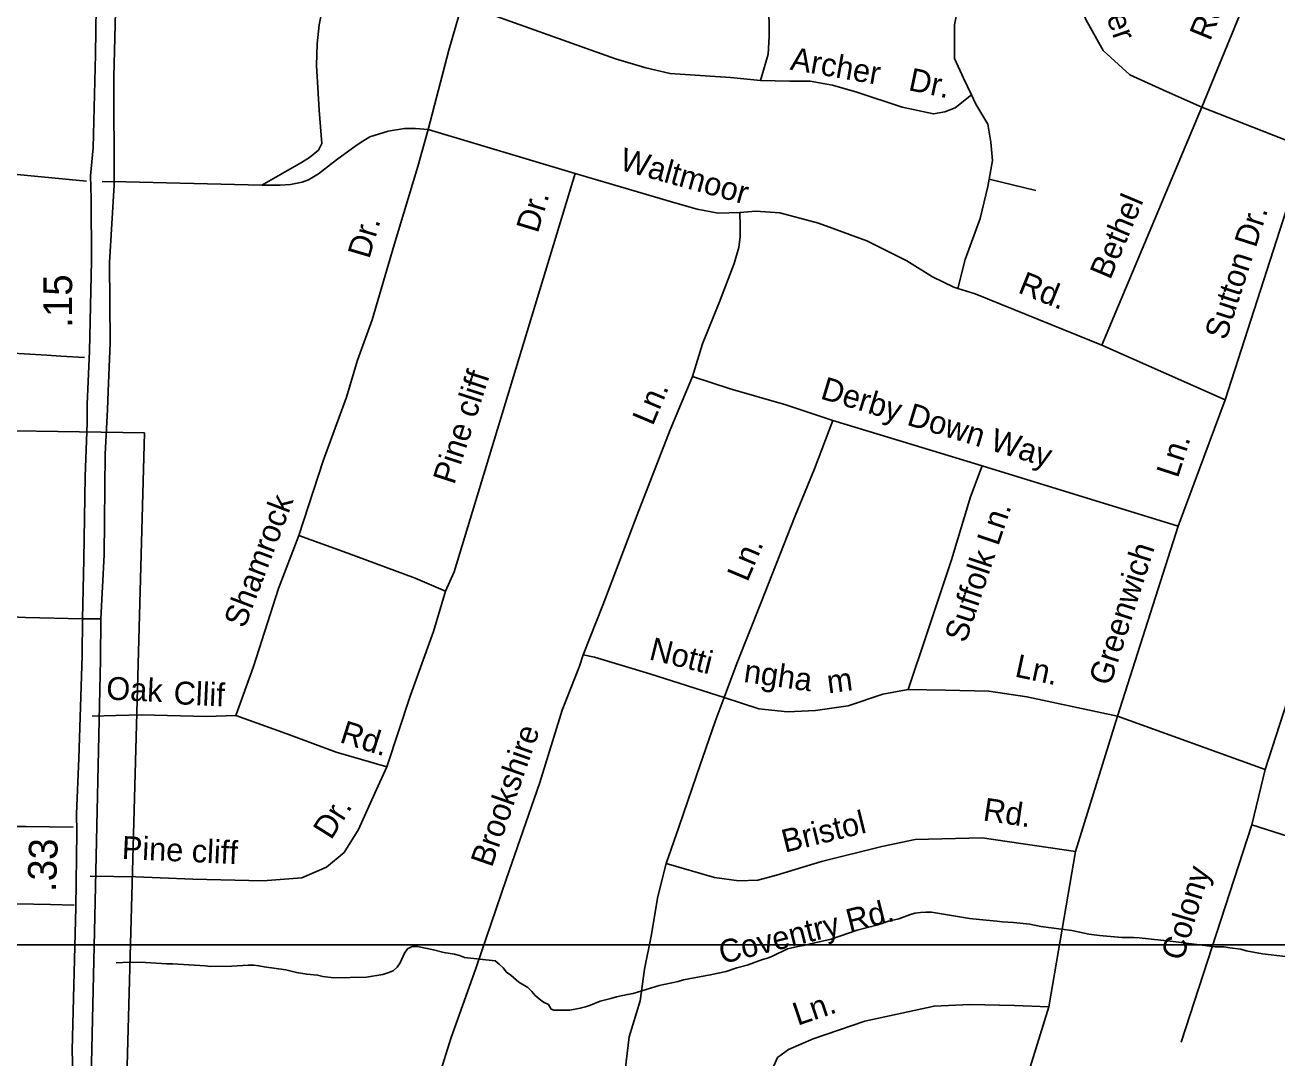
# Model space of a CAD drawing. Extents: x 1945482 to 2853149, y 66427 to 1015778.
# Drawn here: x 2335176 to 2338758, y 154277 to 157233 of the extents above; entities that cross this region are included whole.
import ezdxf

# ---------------------------------------------------------------- set-up
doc = ezdxf.new("R2010")
doc.units = 0
for name, color, linetype in [('Old_Level_10', 7, 'Continuous'), ('Old_Level_17', 7, 'Continuous'), ('Old_Level_29', 7, 'Continuous'), ('Old_Level_32', 7, 'Continuous'), ('Old_Level_35', 7, 'Continuous'), ('Old_Level_48', 7, 'Continuous'), ('Old_Level_49', 7, 'Continuous'), ('Old_Level_59', 7, 'Continuous'), ('Old_Level_63', 7, 'Continuous')]:
    doc.layers.add(name, color=color, linetype=linetype)

msp = doc.modelspace()

# ---------------------------------------------------------------- linework, layer by layer
at = {"layer": 'Old_Level_29'}
for points in [[(2335381.6, 157421.3), (2335377.6, 157148.3), (2335370.7, 156880.9), (2335363, 156800.8), (2335365.2, 156736.3), (2335366.3, 156557.7), (2335360.9, 156300), (2335353.8, 156147.8), (2335353.8, 156094.3), (2335347.9, 155940.6), (2335344.1, 155703.4), (2335340.8, 155534.1)], [(2335393.4, 155533.8), (2335402.8, 155716.4), (2335405.8, 156004.4), (2335411.8, 156132.6), (2335414.3, 156184.4), (2335420.1, 156323.2), (2335417.9, 156553.4), (2335430.8, 156775), (2335430.5, 157084.3), (2335438.7, 157420.3)], [(2335340.8, 155534.1), (2335339.2, 155428.3), (2335330.1, 155134.4), (2335323.4, 154975.9), (2335323.9, 154923.7), (2335321, 154707.7), (2335310.7, 154299.7), (2335312.9, 154231.4), (2335306.8, 154006.8), (2335303.5, 153814.6)], [(2335355.1, 153789.8), (2335366.5, 154261.2), (2335375.6, 154682), (2335391.9, 155416.1), (2335393.4, 155533.8)]]:
    msp.add_lwpolyline(points, dxfattribs=at)
at = {"layer": 'Old_Level_32'}
for points in [[(2335340.8, 155534.1), (2335177.3, 155537.5), (2334739.3, 155558.1), (2334130.3, 155561.6), (2333990.2, 155561.6)], [(2335393.4, 155533.8), (2335340.8, 155534.1)]]:
    msp.add_lwpolyline(points, dxfattribs=at)
at = {"layer": 'Old_Level_35'}
for p, q in [((2338542.8, 156997.6), (2338680.8, 157334.2)), ((2338256.4, 156317.1), (2338542.8, 156997.6)), ((2338542.8, 156997.6), (2338841.2, 156880.5)), ((2336329.3, 156933.8), (2336749.7, 156808.4)), ((2338609.7, 156160.6), (2338841.2, 156880.5)), ((2337934.5, 156791.6), (2338068, 156759.3)), ((2338256.4, 156317.1), (2338609.7, 156160.6)), ((2335346.3, 156281), (2335278.5, 156285.5)), ((2338475.6, 155798.6), (2338609.7, 156160.6)), ((2337914.1, 155971.9), (2338475.6, 155798.6)), ((2338301.3, 155255.3), (2338475.6, 155798.6)), ((2338181.6, 154867.7), (2338301.3, 155255.3)), ((2335245.7, 154938.7), (2335313.4, 154938)), ((2338105.3, 154423.1), (2338181.6, 154867.7)), ((2335316.3, 154714.3), (2335248.6, 154715.9))]:
    msp.add_line(p, q, dxfattribs=at)
for points in [[(2335853.4, 156774.9), (2335967, 156839.4), (2335990.4, 156854.1), (2336015.5, 156875.1), (2336024.9, 156893.6), (2336017.2, 156989.4), (2336010.2, 157117.2), (2336011.7, 157179.2), (2336017.4, 157233.3), (2336044.4, 157364.7), (2336090.4, 157510.6), (2336165.2, 157695.3), (2336268.4, 157923.6), (2336387.3, 158154.4), (2336460.7, 158265.3), (2336598.3, 158428.9), (2336737.4, 158616.6)], [(2329074.5, 157614.2), (2329735.5, 156994.4), (2329904, 156887), (2330064.9, 156787.4), (2330306.6, 156694.5), (2332978.6, 156610), (2333405, 156611), (2333711.5, 156626.4), (2334109.8, 156703), (2334497.5, 156778.2), (2334742.6, 156808.8), (2335033.7, 156816.5), (2335352.2, 156786.3)], [(2337883.5, 157032.6), (2337861.1, 157080.3), (2337835, 157137), (2337835, 157193.7), (2337835, 157232.9), (2337843.7, 157276.5), (2337869.8, 157346.3), (2337900.3, 157433.5), (2337952.6, 157525.1), (2338004.9, 157577.4), (2338083.7, 157611.9)], [(2338083.7, 157611.9), (2338179.7, 157337.5), (2338211.3, 157249), (2338260.9, 157159.9), (2338337.1, 157090.1), (2338441.7, 157042.2), (2338542.8, 156997.6)], [(2336426.3, 157292), (2336388.3, 157161.3), (2336329.3, 156933.8)], [(2336426.3, 157292), (2336865.5, 157135.7)], [(2337280.4, 157074.5), (2337302.6, 157149.7), (2337305.4, 157199.8), (2337305.4, 157244.4), (2337297.1, 157301.5)], [(2336865.5, 157135.7), (2336951.8, 157110.7), (2337021.4, 157094), (2337107.7, 157088.4), (2337194.1, 157082.8), (2337280.4, 157074.5)], [(2337883.5, 157032.6), (2337837.1, 156995.8), (2337807.6, 156984.6), (2337775.5, 156978.6), (2337685.1, 156997.5), (2337556, 157041), (2337486.4, 157060.5), (2337422.4, 157071.7), (2337363.9, 157071.7), (2337280.4, 157074.5)], [(2337934.5, 156791.6), (2337943.9, 156844.8), (2337939.5, 156897.2), (2337930.8, 156949.5), (2337896, 157006.2), (2337883.5, 157032.6)], [(2335397.2, 156785.3), (2335464.8, 156783.7), (2335853.4, 156774.9), (2335905.6, 156775), (2335935.4, 156776.1), (2335969.2, 156783.4), (2335987, 156790), (2336016.2, 156807.2), (2336066.8, 156847.3), (2336123.3, 156887.6), (2336142.2, 156900), (2336162.3, 156913.1), (2336215.5, 156929), (2336261.9, 156936.9), (2336293.5, 156936.9), (2336329.3, 156933.8)], [(2336329.3, 156933.8), (2336299.8, 156828.4), (2336232.1, 156604.2), (2336168.9, 156389.2), (2336127.6, 156273.4), (2336095.6, 156168.1), (2336028.7, 155985.3), (2335959.3, 155772.5)], [(2336379.5, 155613.2), (2336403.6, 155668.3), (2336749.7, 156808.4)], [(2336749.7, 156808.4), (2337041.9, 156721.8), (2337098.7, 156706), (2337159.2, 156694.3), (2337220.8, 156696.7)], [(2337845.3, 156479.3), (2337865.5, 156561.4), (2337909, 156679.1), (2337930.8, 156770.7), (2337934.5, 156791.6)], [(2337220.8, 156696.7), (2337266.9, 156700.5), (2337335.1, 156695.3), (2337446.5, 156665.6), (2337584.4, 156615.2), (2337698.9, 156557.7), (2337772.6, 156512.4), (2337833.8, 156483), (2337845.3, 156479.3)], [(2337085.8, 156227.3), (2337113.9, 156320.3), (2337163.3, 156440.4), (2337205.3, 156550.8), (2337217.9, 156596.2), (2337222.5, 156627.5), (2337222.5, 156657.3), (2337220.8, 156696.7)], [(2337845.3, 156479.3), (2337894.7, 156463.4), (2338256.4, 156317.1)], [(2335278.5, 156285.5), (2335238.5, 156288.1), (2335076, 156297.8), (2334928.2, 156291.9), (2334830.3, 156288), (2334764.7, 156277.6), (2334729.8, 156256.2), (2334698.9, 156222.8), (2334678.6, 156181.9), (2334664.6, 156077.3), (2334666.4, 156017.7)], [(2336773, 155430.5), (2336829.4, 155572.9), (2336927.2, 155830.8), (2337021.6, 156074.7), (2337085.8, 156227.3)], [(2337085.8, 156227.3), (2337193.2, 156191.5), (2337352.9, 156145.9), (2337486.9, 156101)], [(2339240, 156172.5), (2339110.7, 156089.1), (2339067.1, 156034.5), (2339001.8, 155887.3), (2338838.3, 155456.6), (2338723.9, 155102.1), (2338685.7, 154944), (2338484.1, 154322.4)], [(2337176, 155308.6), (2337212.1, 155405.8), (2337281.4, 155578.9), (2337379.5, 155828.6), (2337434.3, 155963.1), (2337486.9, 156101)], [(2337486.9, 156101), (2337622.4, 156060.4), (2337914.1, 155971.9)], [(2337703.1, 155331.4), (2337756.8, 155493.7), (2337826.6, 155702.2), (2337881.5, 155882.6), (2337914.1, 155971.9)], [(2335959.3, 155772.5), (2335901.3, 155620.2), (2335830.1, 155397.5), (2335779.5, 155257.3)], [(2335959.3, 155772.5), (2336097.2, 155722.1), (2336292.1, 155649.7), (2336379.5, 155613.2)], [(2336211.3, 155110.3), (2336279.4, 155315.1), (2336344.4, 155497.6), (2336379.5, 155613.2)], [(2336351.5, 154195.5), (2336394.3, 154333.1), (2336466.4, 154536.1), (2336552.3, 154787.7), (2336649.3, 155065.6), (2336713.3, 155272.2), (2336762.2, 155398.2), (2336773, 155430.5)], [(2336773, 155430.5), (2336805.4, 155423.9), (2336963.2, 155376), (2337176, 155308.6)], [(2337010.6, 154833.7), (2337046.6, 154937.2), (2337096.8, 155085.2), (2337150.8, 155239.6), (2337176, 155308.6)], [(2337176, 155308.6), (2337275.4, 155276.4), (2337357.7, 155267.9), (2337437.7, 155271), (2337531, 155284.6), (2337629.8, 155318.3), (2337703.1, 155331.4)], [(2337703.1, 155331.4), (2337809.5, 155329.7), (2337933.4, 155326.4), (2338042.3, 155310.7), (2338301.3, 155255.3)], [(2335368, 155254.8), (2335435.7, 155256.7), (2335509.3, 155258.7), (2335695.6, 155254), (2335779.5, 155257.3)], [(2335779.5, 155257.3), (2335925.6, 155205), (2336065.9, 155152.4), (2336211.3, 155110.3)], [(2338301.3, 155255.3), (2338723.9, 155102.1)], [(2335362.6, 154797.5), (2335429.9, 154796.5), (2335493.5, 154795.7), (2335655.9, 154788.3), (2335856.3, 154784.1), (2335967.9, 154792.4), (2336038.9, 154823.5), (2336089.1, 154865.5), (2336130.4, 154931.1), (2336176.6, 155035), (2336211.3, 155110.3)], [(2338685.7, 154944), (2339045.3, 154829.5), (2339410.4, 154720.4), (2339587.6, 154667.7)], [(2335248.6, 154715.9), (2335152.6, 154718.2), (2334998.6, 154720.3), (2334930.3, 154721.5), (2334911.9, 154730.7), (2334910.6, 154762.8), (2334916.8, 154913), (2334918.1, 154929.1), (2334928.1, 154933.5), (2334981.7, 154939.5), (2335178, 154939.4), (2335245.7, 154938.7)], [(2337010.6, 154833.7), (2337148.4, 154793.2), (2337218.7, 154784.2), (2337272.8, 154786.3), (2337326, 154800.2), (2337454.8, 154839.4), (2337627, 154882), (2337722.4, 154901.9), (2337914.2, 154907.5), (2338181.6, 154867.7)], [(2336881.9, 154146.6), (2336904.2, 154337.5), (2336936.2, 154440.8), (2336948.7, 154531.3), (2336967, 154625.9), (2336986.5, 154738.9), (2337010.6, 154833.7)], [(2337296.8, 154020.9), (2337306.6, 154179.1), (2337314.2, 154245.7), (2337328.6, 154278.1), (2337359.9, 154301.4), (2337430.5, 154332.1), (2337578.9, 154382.2), (2337777, 154425.8), (2337878.9, 154429.9), (2338007, 154427.1), (2338105.3, 154423.1)], [(2338018, 154049.4), (2338033.9, 154154.1), (2338052.1, 154250.6), (2338105.3, 154423.1)]]:
    msp.add_lwpolyline(points, dxfattribs=at)
at = {"layer": 'Old_Level_48'}
for points in [[(2335517.6, 156066.1), (2334898, 156075.8)], [(2339957.8, 153962.6), (2338392.3, 154026.4), (2338264.7, 153918.4), (2338225.5, 153756.4), (2338245.7, 153020.7), (2338302.5, 152756.7), (2338029.2, 152666.4), (2336836.7, 153157.4), (2336493.1, 153250.7), (2335452.8, 153697.5), (2335517.6, 156066.1)]]:
    msp.add_lwpolyline(points, dxfattribs=at)
at = {"layer": 'Old_Level_49'}
for points in [[(2335517.6, 156066.1), (2334898, 156075.8)], [(2339957.8, 153962.6), (2338392.3, 154026.4), (2338264.7, 153918.4), (2338225.5, 153756.4), (2338245.7, 153020.7), (2338302.5, 152756.7), (2338029.2, 152666.4), (2336836.7, 153157.4), (2336493.1, 153250.7), (2335452.8, 153697.5), (2335517.6, 156066.1)]]:
    msp.add_lwpolyline(points, dxfattribs=at)
at = {"layer": 'Old_Level_59'}
for points in [[(2338782.2, 154567.9), (2338716.5, 154574.8), (2338669.5, 154583.6), (2338654.5, 154588.6), (2338623, 154592.1), (2338606.7, 154595.1), (2338581, 154595.3), (2338461.2, 154610.8), (2338363.5, 154621.1), (2338347, 154622.1), (2338314.7, 154622.2), (2338281.5, 154624.3), (2338250.2, 154627.6), (2338219.2, 154631.6), (2338170.5, 154641.5), (2338082.7, 154652.9), (2338051.2, 154659.9), (2338003.7, 154664.9), (2337971.7, 154666.5), (2337956.7, 154668.7), (2337925.5, 154671.2), (2337878, 154676.3), (2337769.2, 154693.9), (2337753.2, 154694.2), (2337738.2, 154693.5), (2337721.7, 154691.4), (2337706.5, 154686.6), (2337676.5, 154675), (2337646, 154668.4), (2337616.2, 154658.2), (2337556.5, 154642.5), (2337482, 154617.2), (2337435.7, 154606.8), (2337403.7, 154598.7), (2337387.5, 154596.1), (2337357.7, 154589.1), (2337314.5, 154568.5), (2337300.5, 154563), (2337286, 154558.8), (2337242.5, 154542.6), (2337212.2, 154535.5), (2337182.2, 154525), (2337136.5, 154514.8), (2337059.7, 154500.6), (2337044.7, 154495.9), (2336990, 154484.6), (2336915.7, 154461.2), (2336900.2, 154459.2), (2336868, 154452.5), (2336852.5, 154447.3), (2336822, 154439.9), (2336793.5, 154428.2), (2336779.2, 154423.3), (2336764.5, 154419.4), (2336734.5, 154414.1), (2336689.2, 154413.7), (2336681.7, 154417.1), (2336673.7, 154430.1)], [(2336673.7, 154430.1), (2336659.5, 154436.7), (2336647.2, 154445.9), (2336635.7, 154456.1), (2336626.2, 154467.8), (2336615, 154478.7), (2336589.2, 154494.4), (2336565.7, 154513.9), (2336553.5, 154522.6), (2336543.7, 154534.7), (2336533, 154545.3), (2336521.2, 154555.2), (2336433.7, 154564.3), (2336419, 154570.5), (2336404.5, 154574), (2336374.5, 154579.3), (2336344.5, 154586.9), (2336299.2, 154596.4), (2336283.7, 154595.8), (2336270.7, 154589.3), (2336261.7, 154577), (2336249.5, 154549.4), (2336240.7, 154536.8), (2336229, 154526.3), (2336214.5, 154520.3), (2336199.7, 154516.4), (2336153, 154508.5), (2336059.5, 154506.5), (2336028.2, 154510.3), (2336012.7, 154513.9), (2335982.2, 154516.7), (2335952.5, 154521.9), (2335922.7, 154529.3), (2335860.7, 154538), (2335845.5, 154541), (2335830.5, 154542.5), (2335814.5, 154542.7), (2335768.2, 154539.8), (2335706.7, 154538.7), (2335691.5, 154540.5), (2335644.5, 154544), (2335598, 154546.3), (2335582, 154546.2), (2335520.5, 154550.2), (2335474.2, 154551.1), (2335437, 154549.4)]]:
    msp.add_lwpolyline(points, dxfattribs=at)
at = {"layer": 'Old_Level_63'}
msp.add_lwpolyline([(2346064.1, 148689.8), (2332656.4, 148689.8), (2332656.4, 154600.9), (2346064.1, 154600.9)], close=True, dxfattribs=at)

# ---------------------------------------------------------------- texts
at = {"layer": 'Old_Level_10'}
for s, height, rotation, p in [('Amber', 65.62, 289.2832, (2338209.6, 157425.5)), ('Rd.', 65.62, 67.7146, (2338566.3, 157184.8)), ('Archer', 65.62, 350.1287, (2337362.9, 157105.6)), ('Dr.', 65.62, 348.2163, (2337700.9, 157046.8)), ('Waltmoor', 65.62, 344.4351, (2336873.7, 156819.7)), ('Dr.', 65.62, 73.1145, (2336642.9, 156634.9)), ('Bethel', 65.62, 67.174, (2338280.7, 156501.7)), ('Sutton Dr.', 65.62, 72.1808, (2338612, 156328.3)), ('Dr.', 65.62, 73.6355, (2336160.9, 156561.5)), ('Rd.', 65.62, 337.9712, (2338013.9, 156468.3)), ('Pine cliff', 65.62, 72.0648, (2336404, 155915.3)), ('Derby Down Way', 65.617, 343.109, (2337448.7, 156164.6)), ('Ln.', 65.62, 67.1728, (2336971.9, 156083.7)), ('Ln.', 65.62, 72.1808, (2338474.1, 155934.1)), ('Shamrock', 65.62, 69.1577, (2335804.5, 155504.2)), ('Suffolk Ln.', 65.617, 71.4786, (2337867.4, 155462.4)), ('Ln.', 65.62, 67.1821, (2337242.9, 155636.9)), ('Greenwich', 65.62, 72.2092, (2338280.7, 155339.1)), ('Notti', 65.62, 346.0653, (2336958.8, 155418.2)), ('Ln.', 65.62, 347.9215, (2338005.2, 155369)), ('ngha', 65.62, 351.8488, (2337229.9, 155353.3)), ('m ', 65.62, 7.5327, (2337474.5, 155320.2)), ('Oak ', 65.62, 357.4059, (2335407.6, 155302.8)), ('Cllif', 65.62, 357.4059, (2335600.1, 155289.7)), ('Rd.', 65.62, 342.2387, (2336073.4, 155181.4)), ('Brookshire', 65.62, 70.7602, (2336511.4, 154820)), ('Rd.', 65.62, 351.5376, (2337914.5, 154957.2)), ('Dr.', 65.62, 57.7681, (2336051.9, 154898.8)), ('Bristol', 65.62, 13.8867, (2337350.1, 154864.3)), ('Pine cliff', 65.62, 357.4059, (2335452.1, 154846.8)), ('Colony', 65.62, 73.1483, (2338488.2, 154552.6)), ('Coventry Rd.', 65.617, 14.0853, (2337170.5, 154545.6)), ('Ln.', 65.62, 18.6893, (2337386.4, 154369.1))]:
    msp.add_text(s, height=height, rotation=rotation, dxfattribs=at).set_placement(p)
at = {"layer": 'Old_Level_17'}
for s, rotation, p in [('.15', 90.0517, (2335311, 156366.8)), ('.33', 87.6976, (2335264.2, 154751.5))]:
    msp.add_text(s, height=82.02, rotation=rotation, dxfattribs=at).set_placement(p)

doc.saveas('drawing.dxf')
